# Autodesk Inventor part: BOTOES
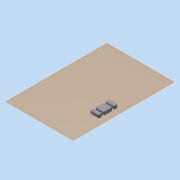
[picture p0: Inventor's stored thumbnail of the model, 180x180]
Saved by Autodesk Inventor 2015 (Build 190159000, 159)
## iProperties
Created: 2015-05
Part Number: BOTOES
Material: Generic
Document SubType Name: Modeling
Designer: TREINA8
Density: 1 g/cm^3
Appearance: Default
Author: TREINA8
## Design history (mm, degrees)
workplane "Work Plane1"
sketch "Sketch1"
  geometry: L1 (42, -3.592)-(31, -3.592) reference; L2 (29.75, -4.842)-(29.75, -7.842) reference; L3 (31, -9.092)-(42, -9.092) reference; L4 (43.25, -7.842)-(43.25, -4.842) reference; L5 (43.25, -23.842)-(43.25, -12.842) reference; L6 (42, -11.592)-(31, -11.592) reference; L7 (29.75, -12.842)-(29.75, -23.842) reference; L8 (31, -25.092)-(42, -25.092) reference; L9 (43.25, -23.842)-(43.25, -12.842) reference; L10 (43.25, -31.842)-(43.25, -28.842) reference; L11 (42, -27.592)-(31, -27.592) reference; L12 (29.75, -28.842)-(29.75, -31.842) reference; L13 (31, -33.092)-(42, -33.092) reference; L14 (43.25, -31.842)-(43.25, -28.842) reference; A1 r 1.25 centre (42, -4.842) between (43.25, -4.842) and (42, -3.592) reference; A2 r 1.25 centre (31, -4.842) between (31, -3.592) and (29.75, -4.842) reference; A3 r 1.25 centre (31, -7.842) between (29.75, -7.842) and (31, -9.092) reference; A4 r 1.25 centre (42, -7.842) between (42, -9.092) and (43.25, -7.842) reference; A5 r 1.25 centre (42, -12.842) between (43.25, -12.842) and (42, -11.592) reference; A6 r 1.25 centre (31, -12.842) between (31, -11.592) and (29.75, -12.842) reference; A7 r 1.25 centre (31, -23.842) between (29.75, -23.842) and (31, -25.092) reference; A8 r 1.25 centre (42, -23.842) between (42, -25.092) and (43.25, -23.842) reference; A9 r 1.25 centre (42, -28.842) between (43.25, -28.842) and (42, -27.592) reference; A10 r 1.25 centre (31, -28.842) between (31, -27.592) and (29.75, -28.842) reference; A11 r 1.25 centre (31, -31.842) between (29.75, -31.842) and (31, -33.092) reference; A12 r 1.25 centre (42, -31.842) between (42, -33.092) and (43.25, -31.842) reference; A13 r 1.25 centre (42, -28.842) between (43.25, -28.842) and (42, -27.592) reference; 1 further point
extrude "Extrusion1" new body sketch "Sketch1" distance "d0" = 5; taper "d1" = 0 deg
fillet "Fillet1" dims "d2" = 1
body "Solid1"
node "Reference1"
node "Reference2"
node "Reference3"
node "Reference4"
node "Reference5"
node "Reference6"
node "Reference7"
node "Reference8"
node "Reference9"
node "Reference10"
node "Reference11"
node "Reference12"
node "Reference13"
node "Reference14"
node "Reference15"
node "Reference16"
node "Reference17"
node "Reference18"
node "Reference19"
node "Reference20"
node "Reference21"
node "Reference22"
node "Reference23"
node "Reference24"
node "Reference25"
node "Reference26"
node "Reference27"
